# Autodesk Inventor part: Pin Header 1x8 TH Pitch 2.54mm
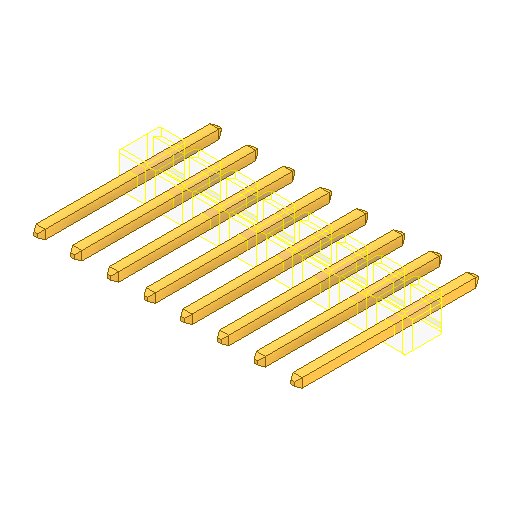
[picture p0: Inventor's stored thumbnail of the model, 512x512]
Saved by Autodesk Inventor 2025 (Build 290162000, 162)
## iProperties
Created: 2025-05
Part Number: Pin Header 1x8 TH Pitch 2.54mm
Material: Acier
Document SubType Name: Modeling
Designer: R5800u
Density: 7.85 g/cm^3
Appearance: Default
Author: R5800u
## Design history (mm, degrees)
feature "Corps1"
feature "Corps2"
feature "Corps3"
feature "Corps4"
feature "Corps5"
feature "Corps6"
feature "Corps7"
feature "Corps8"
feature "Composto1"
node "Solido1"
node "Solido2"
node "Solido3"
node "Solido4"
node "Solido5"
node "Solido6"
node "Solido7"
node "Solido8"
node "Superf1"
